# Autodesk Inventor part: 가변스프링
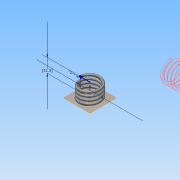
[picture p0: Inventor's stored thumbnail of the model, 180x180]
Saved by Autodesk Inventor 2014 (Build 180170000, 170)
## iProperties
Created: 2015-04
Part Number: 가변스프링
Material: 강철, 탄소
Document SubType Name: Modeling
Designer: Administrator
Density: 7.87 g/cm^3
Appearance: 반연마
Mass: 4.78768 g
Surface Area: 12.5241 cm^2
Volume: 0.608346 cm^3
Author: Administrator
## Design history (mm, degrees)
sketch "스케치1"
  geometry: L1 (0, 0)-(-8, 0); L2 (-8, 0)-(-8, -11.5); L3 (-8, -11.5)-(0, -11.5); L4 (0, -11.5)-(0, 0); C1 r 1 at (-8, 0)
  constraints: 8 end point, 2 parallel, 1 centre point, 1 coincident, 1 horizontal, 1 perpendicular
  dimensions: "d0" = 16 diameter of L2 L4; "d1" = 11.50049 distance between parallel lines of L3 L1 (derived); "d2" = 2 diameter of C1
feature "코일1" pitch "d3" = 10; turns "d5" = 4; dims "d4" = 11.50049 (= d1), "d6" = 0, angle "d7" = 90 deg, angle "d8" = 90 deg, "d9" = 0, "d10" = 0
sketch "스케치2"
  geometry: L1 (7, 0)-(9, 0) reference; 1 further point
  constraints: 1 horizontal alignment
extrude "돌출1" cut sketch "스케치2" stored distance "d11" = 10; taper "d12" = 0 deg
node "작업 평면1"
sketch "스케치3"
  geometry: L1 (9, 0)-(7, 0) reference; 1 further point
  constraints: 1 horizontal alignment
extrude "돌출2" cut sketch "스케치3" stored distance "d13" = 10; taper "d14" = 0 deg
node "솔리드1"
node "절단 모서리 투영1"
node "절단 모서리 투영2"
